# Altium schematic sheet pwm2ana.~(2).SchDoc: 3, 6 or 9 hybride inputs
size A4; Revision: V0.1; SheetNumber: 1; SheetTotal: 1; PageSetup: Record=PageOptions¦CenterHorizontal=True¦CenterVertical=True¦PrintScale=1.00¦XCorrection=1.00¦YCorrection=1.00¦PrintKind=2¦BorderSize=5000000¦LeftOffset=0¦BottomOffset=0¦Orientation=2¦PaperLength=1000¦PaperWidth=1000¦Scale=100¦PaperSource=7¦PrintQuality=-4¦MediaType=1¦DitherType=10¦PaperKind=A4¦PrintScaleMode=1
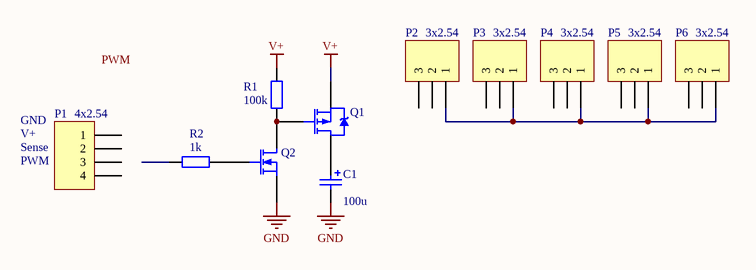
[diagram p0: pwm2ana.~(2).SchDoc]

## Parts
C1  100u  [POLAR0.8]
P1  4x2.54  [HDR1X4]
P2  3x2.54  [HDR1X3]
P3  3x2.54  [HDR1X3]
P4  3x2.54  [HDR1X3]
P5  3x2.54  [HDR1X3]
P6  3x2.54  [HDR1X3]
Q1  PMOS-2  [TO-220AB]  (value not drawn)
Q2  MOSFET-N  [E3]  (value not drawn)
R1  100k  [R0402]
R2  1k  [R0402]

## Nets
GND: C1.2 Q2.3(S)
V+: Q1.3(S) R1.1
NetC1_1: C1.1 Q1.2(D)
NetP2_1: P2.1 P3.1 P4.1 P5.1 P6.1
NetQ1_1: Q1.1(G) Q2.1(D) R1.2
NetQ2_2: Q2.2(G) R2.2

Not connected (* = marked no-connect by the designer): P1 1 2 3 4; P2 2 3; P3 2 3; P4 2 3; P5 2 3; P6 2 3; R2 1

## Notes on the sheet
- GND
- V+
- (near P1) Sense
- PWM
- Labels drawn without touching a wire or pin: PWM

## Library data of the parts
C1 = Cap Pol2: Polarized Capacitor (Axial)
P1 = Header 4: Header, 4-Pin
P2-P6 = Header 3: Header, 3-Pin
Q1 = PMOS-2: P-Channel Power MOSFET; Note: Pin 4 not drawn and electrically connected to Pin 2.
Q2 = MOSFET-N: N-Channel MOSFET
R1 R2 = Res2: Resistor; Manufacturer: MULTICOMP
